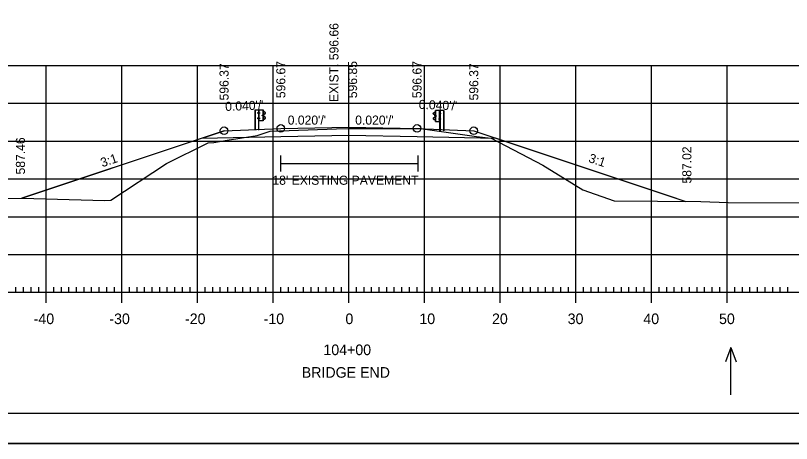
# Model space of a CAD drawing. Extents: x 961436 to 1372525, y 380079 to 2027791.
# Drawn here: x 1371150.8 to 1371253.4, y 380322.4 to 380379 of the extents above; entities that cross this region are included whole.
import ezdxf

# ---------------------------------------------------------------- set-up
doc = ezdxf.new("R2010")
doc.units = 0
for name, color, linetype in [('R_Alt Surface', 7, 'Continuous'), ('R_Axis', 7, 'Continuous'), ('R_Axis Annot', 7, 'Continuous'), ('R_Border', 7, 'Continuous'), ('R_Drive', 7, 'Continuous'), ('R_Exist Surface', 7, 'Continuous'), ('R_Fin Surface', 7, 'Continuous'), ('R_Fin Surface Annot', 7, 'Continuous'), ('R_Grid', 7, 'Continuous'), ('R_No Plot', 7, 'Continuous'), ('R_Proposed Road', 7, 'Continuous'), ('R_Water Annot', 7, 'Continuous'), ('R_Xsect Elev', 7, 'Continuous')]:
    doc.layers.add(name, color=color, linetype=linetype)

msp = doc.modelspace()

# ---------------------------------------------------------------- linework, layer by layer
at = {"layer": 'R_Alt Surface'}
for points in [[(1371178.38, 380363.77), (1371175.88, 380362.93)], [(1371211.38, 380363.77), (1371213.88, 380362.93)], [(1371175.88, 380362.93), (1371151.65, 380354.86)], [(1371175.4, 380362.77), (1371185.88, 380362.98), (1371194.88, 380363.16), (1371203.88, 380362.98), (1371214.36, 380362.77)], [(1371213.88, 380362.93), (1371239.42, 380354.42)]]:
    msp.add_lwpolyline(points, dxfattribs=at)
at = {"layer": 'R_Axis'}
for p, q in [((1371150.88, 380342.4), (1371150.88, 380343.1)), ((1371151.88, 380342.4), (1371151.88, 380343.1)), ((1371152.88, 380342.4), (1371152.88, 380343.1)), ((1371153.88, 380342.4), (1371153.88, 380343.1)), ((1371154.88, 380341), (1371154.88, 380343.8)), ((1371155.88, 380342.4), (1371155.88, 380343.1)), ((1371156.88, 380342.4), (1371156.88, 380343.1)), ((1371157.88, 380342.4), (1371157.88, 380343.1)), ((1371158.88, 380342.4), (1371158.88, 380343.1)), ((1371159.88, 380342.4), (1371159.88, 380343.1)), ((1371160.88, 380342.4), (1371160.88, 380343.1)), ((1371161.88, 380342.4), (1371161.88, 380343.1)), ((1371162.88, 380342.4), (1371162.88, 380343.1)), ((1371163.88, 380342.4), (1371163.88, 380343.1)), ((1371164.88, 380341), (1371164.88, 380343.8)), ((1371165.88, 380342.4), (1371165.88, 380343.1)), ((1371166.88, 380342.4), (1371166.88, 380343.1)), ((1371167.88, 380342.4), (1371167.88, 380343.1)), ((1371168.88, 380342.4), (1371168.88, 380343.1)), ((1371169.88, 380342.4), (1371169.88, 380343.1)), ((1371170.88, 380342.4), (1371170.88, 380343.1)), ((1371171.88, 380342.4), (1371171.88, 380343.1)), ((1371172.88, 380342.4), (1371172.88, 380343.1)), ((1371173.88, 380342.4), (1371173.88, 380343.1)), ((1371174.88, 380341), (1371174.88, 380343.8)), ((1371175.88, 380342.4), (1371175.88, 380343.1)), ((1371176.88, 380342.4), (1371176.88, 380343.1)), ((1371177.88, 380342.4), (1371177.88, 380343.1)), ((1371178.88, 380342.4), (1371178.88, 380343.1)), ((1371179.88, 380342.4), (1371179.88, 380343.1)), ((1371180.88, 380342.4), (1371180.88, 380343.1)), ((1371181.88, 380342.4), (1371181.88, 380343.1)), ((1371182.88, 380342.4), (1371182.88, 380343.1)), ((1371183.88, 380342.4), (1371183.88, 380343.1)), ((1371184.88, 380341), (1371184.88, 380343.8)), ((1371185.88, 380342.4), (1371185.88, 380343.1)), ((1371186.88, 380342.4), (1371186.88, 380343.1)), ((1371187.88, 380342.4), (1371187.88, 380343.1)), ((1371188.88, 380342.4), (1371188.88, 380343.1)), ((1371189.88, 380342.4), (1371189.88, 380343.1)), ((1371190.88, 380342.4), (1371190.88, 380343.1)), ((1371191.88, 380342.4), (1371191.88, 380343.1)), ((1371192.88, 380342.4), (1371192.88, 380343.1)), ((1371193.88, 380342.4), (1371193.88, 380343.1)), ((1371194.88, 380341), (1371194.88, 380343.8)), ((1371195.88, 380342.4), (1371195.88, 380343.1)), ((1371196.88, 380342.4), (1371196.88, 380343.1)), ((1371197.88, 380342.4), (1371197.88, 380343.1)), ((1371198.88, 380342.4), (1371198.88, 380343.1)), ((1371199.88, 380342.4), (1371199.88, 380343.1)), ((1371200.88, 380342.4), (1371200.88, 380343.1)), ((1371201.88, 380342.4), (1371201.88, 380343.1)), ((1371202.88, 380342.4), (1371202.88, 380343.1)), ((1371203.88, 380342.4), (1371203.88, 380343.1)), ((1371204.88, 380341), (1371204.88, 380343.8)), ((1371205.88, 380342.4), (1371205.88, 380343.1)), ((1371206.88, 380342.4), (1371206.88, 380343.1)), ((1371207.88, 380342.4), (1371207.88, 380343.1)), ((1371208.88, 380342.4), (1371208.88, 380343.1)), ((1371209.88, 380342.4), (1371209.88, 380343.1)), ((1371210.88, 380342.4), (1371210.88, 380343.1)), ((1371211.88, 380342.4), (1371211.88, 380343.1)), ((1371212.88, 380342.4), (1371212.88, 380343.1)), ((1371213.88, 380342.4), (1371213.88, 380343.1)), ((1371214.88, 380341), (1371214.88, 380343.8)), ((1371215.88, 380342.4), (1371215.88, 380343.1)), ((1371216.88, 380342.4), (1371216.88, 380343.1)), ((1371217.88, 380342.4), (1371217.88, 380343.1)), ((1371218.88, 380342.4), (1371218.88, 380343.1)), ((1371219.88, 380342.4), (1371219.88, 380343.1)), ((1371220.88, 380342.4), (1371220.88, 380343.1)), ((1371221.88, 380342.4), (1371221.88, 380343.1)), ((1371222.88, 380342.4), (1371222.88, 380343.1)), ((1371223.88, 380342.4), (1371223.88, 380343.1)), ((1371224.88, 380341), (1371224.88, 380343.8)), ((1371225.88, 380342.4), (1371225.88, 380343.1)), ((1371226.88, 380342.4), (1371226.88, 380343.1)), ((1371227.88, 380342.4), (1371227.88, 380343.1)), ((1371228.88, 380342.4), (1371228.88, 380343.1)), ((1371229.88, 380342.4), (1371229.88, 380343.1)), ((1371230.88, 380342.4), (1371230.88, 380343.1)), ((1371231.88, 380342.4), (1371231.88, 380343.1)), ((1371232.88, 380342.4), (1371232.88, 380343.1)), ((1371233.88, 380342.4), (1371233.88, 380343.1)), ((1371234.88, 380341), (1371234.88, 380343.8)), ((1371235.88, 380342.4), (1371235.88, 380343.1)), ((1371236.88, 380342.4), (1371236.88, 380343.1)), ((1371237.88, 380342.4), (1371237.88, 380343.1)), ((1371238.88, 380342.4), (1371238.88, 380343.1)), ((1371239.88, 380342.4), (1371239.88, 380343.1)), ((1371240.88, 380342.4), (1371240.88, 380343.1)), ((1371241.88, 380342.4), (1371241.88, 380343.1)), ((1371242.88, 380342.4), (1371242.88, 380343.1)), ((1371243.88, 380342.4), (1371243.88, 380343.1)), ((1371244.88, 380341), (1371244.88, 380343.8)), ((1371245.88, 380342.4), (1371245.88, 380343.1)), ((1371246.88, 380342.4), (1371246.88, 380343.1)), ((1371247.88, 380342.4), (1371247.88, 380343.1)), ((1371248.88, 380342.4), (1371248.88, 380343.1)), ((1371249.88, 380342.4), (1371249.88, 380343.1)), ((1371250.88, 380342.4), (1371250.88, 380343.1)), ((1371251.88, 380342.4), (1371251.88, 380343.1)), ((1371252.88, 380342.4), (1371252.88, 380343.1)), ((1371054.88, 380342.4), (1371334.88, 380342.4))]:
    msp.add_line(p, q, dxfattribs=at)
at = {"layer": 'R_Border'}
msp.add_line((1371353.06, 380326.4), (1371036.88, 380326.4), dxfattribs=at)
at = {"layer": 'R_Drive'}
for p, q in [((1371185.86, 380360.5), (1371185.86, 380358.37)), ((1371203.99, 380360.5), (1371203.99, 380358.37)), ((1371185.86, 380359.43), (1371203.99, 380359.43))]:
    msp.add_line(p, q, dxfattribs=at)
at = {"layer": 'R_Exist Surface'}
msp.add_lwpolyline([(1371146.47, 380354.82), (1371151.66, 380354.86), (1371162.64, 380354.55), (1371163.42, 380354.6), (1371170.77, 380359.44), (1371176.27, 380362.18), (1371177.03, 380362.19), (1371178.78, 380362.51), (1371182.76, 380363.15), (1371184.49, 380363.69), (1371193.23, 380364.01), (1371194.9, 380364.06), (1371196.9, 380364.05), (1371204.33, 380364.04), (1371211.76, 380363.01), (1371213.66, 380362.76), (1371220.5, 380359.2), (1371225.8, 380355.96), (1371229.93, 380354.49), (1371241.4, 380354.4), (1371245, 380354.27), (1371258.13, 380354.22)], dxfattribs=at)
at = {"layer": 'R_Fin Surface'}
for points in [[(1371151.65, 380354.86), (1371175.4, 380362.77), (1371175.88, 380362.93), (1371178.38, 380363.77), (1371185.88, 380364.07), (1371194.88, 380364.25), (1371203.88, 380364.07), (1371211.38, 380363.77), (1371213.88, 380362.93), (1371214.36, 380362.77), (1371236.92, 380355.25), (1371239.42, 380354.42)], [(1371178.38, 380363.77), (1371185.88, 380364.07), (1371194.88, 380364.25), (1371203.88, 380364.07), (1371211.38, 380363.77)]]:
    msp.add_lwpolyline(points, dxfattribs=at)
at = {"layer": 'R_Grid'}
for p, q in [((1371054.88, 380372.4), (1371334.88, 380372.4)), ((1371154.88, 380342.4), (1371154.88, 380372.4)), ((1371164.88, 380342.4), (1371164.88, 380372.4)), ((1371174.88, 380342.4), (1371174.88, 380372.4)), ((1371184.88, 380342.4), (1371184.88, 380372.4)), ((1371194.88, 380342.4), (1371194.88, 380372.4)), ((1371204.88, 380342.4), (1371204.88, 380372.4)), ((1371214.88, 380342.4), (1371214.88, 380372.4)), ((1371224.88, 380342.4), (1371224.88, 380372.4)), ((1371234.88, 380342.4), (1371234.88, 380372.4)), ((1371244.88, 380342.4), (1371244.88, 380372.4)), ((1371054.88, 380367.4), (1371334.88, 380367.4)), ((1371054.88, 380362.4), (1371334.88, 380362.4)), ((1371054.88, 380357.4), (1371334.88, 380357.4)), ((1371054.88, 380352.4), (1371334.88, 380352.4)), ((1371054.88, 380347.4), (1371334.88, 380347.4)), ((1371054.88, 380342.4), (1371334.88, 380342.4))]:
    msp.add_line(p, q, dxfattribs=at)
at = {"layer": 'R_No Plot'}
msp.add_line((1371024.48, 380322.42), (1371357.81, 380322.42), dxfattribs=at)
for points in [[(1371024.47, 380535.75), (1371357.81, 380535.75), (1371357.81, 380322.41), (1371024.47, 380322.41)], [(1371270.8, 380531.86), (1371290.42, 380531.86), (1371290.42, 380521.98), (1371306.53, 380521.98), (1371329.73, 380521.98), (1371329.85, 380493.82), (1371353.06, 380493.82), (1371353.06, 380326.4), (1371036.88, 380326.4), (1371036.88, 380531.86)]]:
    msp.add_lwpolyline(points, close=True, dxfattribs=at)
for centre in [(1371185.88, 380364.07), (1371203.88, 380364.07), (1371178.38, 380363.77), (1371211.38, 380363.77)]:
    msp.add_circle(centre, 0.5, dxfattribs=at)
at = {"layer": 'R_Proposed Road'}
for p, q in [((1371182.44, 380366.52), (1371182.44, 380363.85)), ((1371182.47, 380366.52), (1371182.47, 380363.85)), ((1371182.93, 380366.2), (1371182.87, 380366.2)), ((1371182.87, 380366.08), (1371182.87, 380366.18)), ((1371182.93, 380366.17), (1371182.87, 380366.17)), ((1371182.93, 380366.1), (1371182.87, 380366.1)), ((1371182.93, 380366.06), (1371182.87, 380366.06)), ((1371182.93, 380366.1), (1371182.88, 380366.1)), ((1371183, 380366.52), (1371182.93, 380366.52)), ((1371182.93, 380366.06), (1371182.93, 380366.2)), ((1371182.96, 380363.85), (1371182.96, 380366.52)), ((1371183, 380366.52), (1371182.99, 380366.52)), ((1371183.06, 380366.13), (1371183, 380366.13)), ((1371183.01, 380366.19), (1371183.06, 380366.19)), ((1371183.01, 380366.06), (1371183.06, 380366.06)), ((1371183.06, 380366.19), (1371183.06, 380366.06)), ((1371183.46, 380365.74), (1371183.46, 380365.84)), ((1371183.52, 380365.82), (1371183.46, 380365.82)), ((1371183.52, 380365.76), (1371183.46, 380365.76)), ((1371183.52, 380365.72), (1371183.46, 380365.72)), ((1371183.52, 380365.86), (1371183.47, 380365.86)), ((1371183.52, 380365.76), (1371183.47, 380365.76)), ((1371183.52, 380365.72), (1371183.52, 380365.86)), ((1371183.53, 380365.07), (1371183.53, 380366.51)), ((1371183.68, 380366.29), (1371183.56, 380366.35)), ((1371183.67, 380366.27), (1371183.57, 380366.33)), ((1371183.57, 380365.72), (1371183.57, 380365.86)), ((1371183.6, 380365.72), (1371183.6, 380365.86)), ((1371183.62, 380365.94), (1371183.8, 380366.05)), ((1371183.78, 380365.54), (1371183.62, 380365.65)), ((1371183.79, 380365.56), (1371183.63, 380365.67)), ((1371183.64, 380365.92), (1371183.82, 380366.03)), ((1371183.81, 380366.16), (1371183.67, 380366.27)), ((1371183.82, 380366.18), (1371183.68, 380366.29)), ((1371206.03, 380366.1), (1371206.17, 380366.21)), ((1371206.22, 380365.84), (1371206.04, 380365.95)), ((1371206.05, 380366.08), (1371206.18, 380366.19)), ((1371206.23, 380365.86), (1371206.05, 380365.97)), ((1371206.17, 380366.21), (1371206.29, 380366.27)), ((1371206.18, 380366.19), (1371206.28, 380366.25)), ((1371206.26, 380365.64), (1371206.25, 380365.78)), ((1371206.28, 380365.64), (1371206.28, 380365.78)), ((1371206.32, 380364.99), (1371206.32, 380366.43)), ((1371206.34, 380365.64), (1371206.34, 380365.78)), ((1371206.34, 380365.78), (1371206.39, 380365.78)), ((1371206.34, 380365.74), (1371206.39, 380365.74)), ((1371206.34, 380365.68), (1371206.38, 380365.68)), ((1371206.34, 380365.68), (1371206.39, 380365.68)), ((1371206.34, 380365.64), (1371206.39, 380365.64)), ((1371206.4, 380365.66), (1371206.4, 380365.76)), ((1371206.85, 380366.11), (1371206.79, 380366.11)), ((1371206.79, 380366.11), (1371206.79, 380365.98)), ((1371206.85, 380365.98), (1371206.79, 380365.98)), ((1371206.8, 380366.05), (1371206.85, 380366.05)), ((1371206.85, 380366.44), (1371206.86, 380366.44)), ((1371206.85, 380366.44), (1371206.93, 380366.44)), ((1371206.89, 380363.77), (1371206.89, 380366.44)), ((1371206.93, 380365.98), (1371206.93, 380366.12)), ((1371206.93, 380366.12), (1371206.98, 380366.12)), ((1371206.93, 380366.09), (1371206.98, 380366.09)), ((1371206.93, 380366.02), (1371206.97, 380366.02)), ((1371206.93, 380366.02), (1371206.98, 380366.02)), ((1371206.93, 380365.98), (1371206.98, 380365.98)), ((1371206.99, 380366), (1371206.99, 380366.1)), ((1371207.38, 380366.44), (1371207.38, 380363.77)), ((1371207.41, 380366.44), (1371207.41, 380363.77)), ((1371182.92, 380365.47), (1371182.86, 380365.47)), ((1371182.86, 380365.35), (1371182.86, 380365.45)), ((1371182.92, 380365.43), (1371182.86, 380365.43)), ((1371182.92, 380365.37), (1371182.86, 380365.37)), ((1371182.92, 380365.33), (1371182.86, 380365.33)), ((1371182.92, 380365.37), (1371182.87, 380365.37)), ((1371182.92, 380365.33), (1371182.92, 380365.47)), ((1371183, 380365.07), (1371182.96, 380365.07)), ((1371183.06, 380365.4), (1371183, 380365.4)), ((1371183.06, 380365.47), (1371183.01, 380365.47)), ((1371183.06, 380365.33), (1371183.01, 380365.33)), ((1371183.06, 380365.33), (1371183.06, 380365.47)), ((1371183.56, 380365.24), (1371183.67, 380365.3)), ((1371183.57, 380365.22), (1371183.69, 380365.28)), ((1371183.67, 380365.3), (1371183.81, 380365.41)), ((1371183.69, 380365.28), (1371183.82, 380365.4)), ((1371206.16, 380365.2), (1371206.03, 380365.32)), ((1371206.18, 380365.22), (1371206.05, 380365.33)), ((1371206.06, 380365.48), (1371206.22, 380365.59)), ((1371206.07, 380365.46), (1371206.24, 380365.57)), ((1371206.29, 380365.14), (1371206.16, 380365.2)), ((1371206.29, 380365.16), (1371206.18, 380365.22)), ((1371206.79, 380365.25), (1371206.79, 380365.39)), ((1371206.79, 380365.39), (1371206.85, 380365.39)), ((1371206.79, 380365.25), (1371206.85, 380365.25)), ((1371206.8, 380365.32), (1371206.85, 380365.32)), ((1371206.85, 380364.99), (1371206.89, 380364.99)), ((1371206.94, 380365.25), (1371206.94, 380365.39)), ((1371206.94, 380365.39), (1371206.99, 380365.39)), ((1371206.94, 380365.35), (1371206.99, 380365.35)), ((1371206.94, 380365.29), (1371206.98, 380365.29)), ((1371206.94, 380365.29), (1371206.99, 380365.29)), ((1371206.94, 380365.25), (1371206.99, 380365.25)), ((1371207, 380365.27), (1371207, 380365.37))]:
    msp.add_line(p, q, dxfattribs=at)
for points in [[(1371182.44, 380366.52), (1371182.93, 380366.52), (1371182.93, 380363.85)], [(1371207.41, 380366.44), (1371206.93, 380366.44), (1371206.93, 380363.77)]]:
    msp.add_lwpolyline(points, dxfattribs=at)
for points in [[(1371182.87, 380366.16), (1371182.87, 380366.1), (1371182.84, 380366.1), (1371182.84, 380366.16)], [(1371182.92, 380366.22), (1371182.92, 380366.04), (1371182.94, 380366.04), (1371182.94, 380366.22)], [(1371183.56, 380366.52), (1371183.56, 380365.07), (1371183, 380365.07), (1371183, 380366.52)], [(1371183.06, 380366.19), (1371183.06, 380366.06), (1371183, 380366.06), (1371183, 380366.19)], [(1371183.46, 380365.82), (1371183.46, 380365.76), (1371183.43, 380365.76), (1371183.43, 380365.82)], [(1371183.52, 380365.88), (1371183.52, 380365.7), (1371183.53, 380365.7), (1371183.53, 380365.88)], [(1371206.3, 380366.44), (1371206.3, 380364.99), (1371206.85, 380364.99), (1371206.85, 380366.44)], [(1371206.34, 380365.8), (1371206.34, 380365.62), (1371206.33, 380365.62), (1371206.33, 380365.8)], [(1371206.4, 380365.74), (1371206.4, 380365.68), (1371206.42, 380365.68), (1371206.42, 380365.74)], [(1371206.8, 380366.11), (1371206.8, 380365.98), (1371206.85, 380365.98), (1371206.85, 380366.11)], [(1371206.93, 380366.14), (1371206.93, 380365.96), (1371206.92, 380365.96), (1371206.92, 380366.14)], [(1371206.99, 380366.08), (1371206.99, 380366.02), (1371207.01, 380366.02), (1371207.01, 380366.08)], [(1371182.85, 380365.43), (1371182.85, 380365.37), (1371182.83, 380365.37), (1371182.83, 380365.43)], [(1371182.91, 380365.49), (1371182.91, 380365.31), (1371182.92, 380365.31), (1371182.92, 380365.49)], [(1371183.06, 380365.47), (1371183.06, 380365.33), (1371183, 380365.33), (1371183, 380365.47)], [(1371206.8, 380365.39), (1371206.8, 380365.25), (1371206.85, 380365.25), (1371206.85, 380365.39)], [(1371206.94, 380365.41), (1371206.94, 380365.23), (1371206.93, 380365.23), (1371206.93, 380365.41)], [(1371207, 380365.35), (1371207, 380365.29), (1371207.03, 380365.29), (1371207.03, 380365.35)]]:
    msp.add_lwpolyline(points, close=True, dxfattribs=at)
for centre, radius, start, end in [((1371182.89, 380366.18), 0.0234, 134.5745, 222.2244), ((1371182.97, 380366.13), 0.0979, 159.7423, 200.2577), ((1371182.89, 380366.08), 0.0265, 140.9334, 216.6234), ((1371183.48, 380365.84), 0.0234, 134.5745, 222.2244), ((1371183.56, 380365.79), 0.0979, 159.7423, 200.2577), ((1371183.48, 380365.74), 0.0265, 140.9334, 216.6234), ((1371183.66, 380365.86), 0.0918, 118.106, 175.0444), ((1371183.65, 380365.71), 0.0747, 171.7804, 246.8536), ((1371183.59, 380365.79), 0.0481, 282.9554, 86.0697), ((1371183.66, 380365.86), 0.066, 118.106, 175.0444), ((1371183.65, 380365.71), 0.049, 171.7804, 246.8536), ((1371183.77, 380366.11), 0.0658, 299.2499, 57.9783), ((1371183.77, 380366.11), 0.0909, 299.2499, 57.9783), ((1371206.08, 380366.03), 0.0909, 122.0217, 240.7501), ((1371206.08, 380366.03), 0.0658, 122.0217, 240.7501), ((1371206.26, 380365.71), 0.0481, 93.9303, 257.0446), ((1371206.19, 380365.78), 0.066, 4.9556, 61.894), ((1371206.19, 380365.78), 0.0918, 4.9556, 61.894), ((1371206.21, 380365.63), 0.049, 293.1464, 8.2196), ((1371206.21, 380365.63), 0.0747, 293.1464, 8.2196), ((1371206.37, 380365.76), 0.0234, 317.7756, 45.4255), ((1371206.3, 380365.71), 0.0979, 339.7423, 20.2577), ((1371206.37, 380365.66), 0.0265, 323.3766, 39.0666), ((1371206.96, 380366.1), 0.0234, 317.7756, 45.4255), ((1371206.89, 380366.05), 0.0979, 339.7423, 20.2577), ((1371206.96, 380366), 0.0265, 323.3766, 39.0666), ((1371182.88, 380365.45), 0.0234, 134.5745, 222.2244), ((1371182.95, 380365.4), 0.0979, 159.7423, 200.2577), ((1371182.88, 380365.35), 0.0265, 140.9334, 216.6234), ((1371183.73, 380365.46), 0.0907, 325.2184, 59.12), ((1371183.73, 380365.46), 0.116, 325.2184, 59.12), ((1371206.12, 380365.38), 0.116, 120.88, 214.7816), ((1371206.12, 380365.38), 0.0907, 120.88, 214.7816), ((1371206.97, 380365.37), 0.0234, 317.7756, 45.4255), ((1371206.9, 380365.32), 0.0979, 339.7423, 20.2577), ((1371206.97, 380365.27), 0.0265, 323.3766, 39.0666)]:
    msp.add_arc(centre, radius, start, end, dxfattribs=at)
at = {"layer": 'R_Water Annot'}
for p, q in [((1371245.35, 380335.12), (1371244.65, 380333.2)), ((1371245.35, 380328.84), (1371245.35, 380335.12)), ((1371245.35, 380335.12), (1371246.05, 380333.2))]:
    msp.add_line(p, q, dxfattribs=at)

# ---------------------------------------------------------------- texts
at = {"layer": 'R_Axis Annot'}
for s, p in [('-40', (1371153.22, 380338.2)), ('-30', (1371163.22, 380338.2)), ('-20', (1371173.22, 380338.2)), ('-10', (1371183.61, 380338.2)), ('0', (1371194.42, 380338.2)), ('10', (1371204.19, 380338.2)), ('20', (1371213.79, 380338.2)), ('30', (1371223.79, 380338.2)), ('40', (1371233.79, 380338.2)), ('50', (1371243.79, 380338.2)), ('104+00', (1371191.51, 380334.1)), ('BRIDGE END', (1371188.65, 380331.11))]:
    msp.add_text(s, height=1.4, dxfattribs=at).set_placement(p)
at = {"layer": 'R_Fin Surface Annot'}
for s, rotation, p in [('596.67', 90, (1371186.48, 380368.07)), ('596.85', 90, (1371195.96, 380368.07)), ('596.67', 90, (1371204.48, 380368.07)), ('596.37', 90, (1371178.98, 380367.77)), ('596.37', 90, (1371211.98, 380367.77)), ("0.040'/'", 2.2906, (1371178.55, 380366.37)), ("0.040'/'", 357.7094, (1371204.09, 380366.66)), ("0.020'/'", 360, (1371186.79, 380364.57)), ("0.020'/'", 360, (1371195.71, 380364.57)), ('587.46', 90, (1371152.07, 380357.98)), ('587.02', 90, (1371240.14, 380356.78)), ('3:1', 18.4349, (1371162.29, 380358.93)), ('3:1', 341.5651, (1371226.46, 380359.65))]:
    msp.add_text(s, height=1.2, rotation=rotation, dxfattribs=at).set_placement(p)
msp.add_text("18' EXISTING PAVEMENT", height=1.2, dxfattribs=at).set_placement((1371184.77, 380356.62))
at = {"layer": 'R_Xsect Elev'}
msp.add_text('EXIST. 596.66', height=1.2, rotation=90, dxfattribs=at).set_placement((1371193.5, 380367.56))

doc.saveas('drawing.dxf')
